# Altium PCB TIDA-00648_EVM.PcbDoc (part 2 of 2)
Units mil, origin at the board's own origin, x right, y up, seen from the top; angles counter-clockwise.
Board outline 2200 x 2000 mil, 4 copper layers (Component Side, Ground Plane, Power Plane, Solder Side), stack 55.6 mil thick; 91 components, 64 nets, 274 pads, 141 vias.
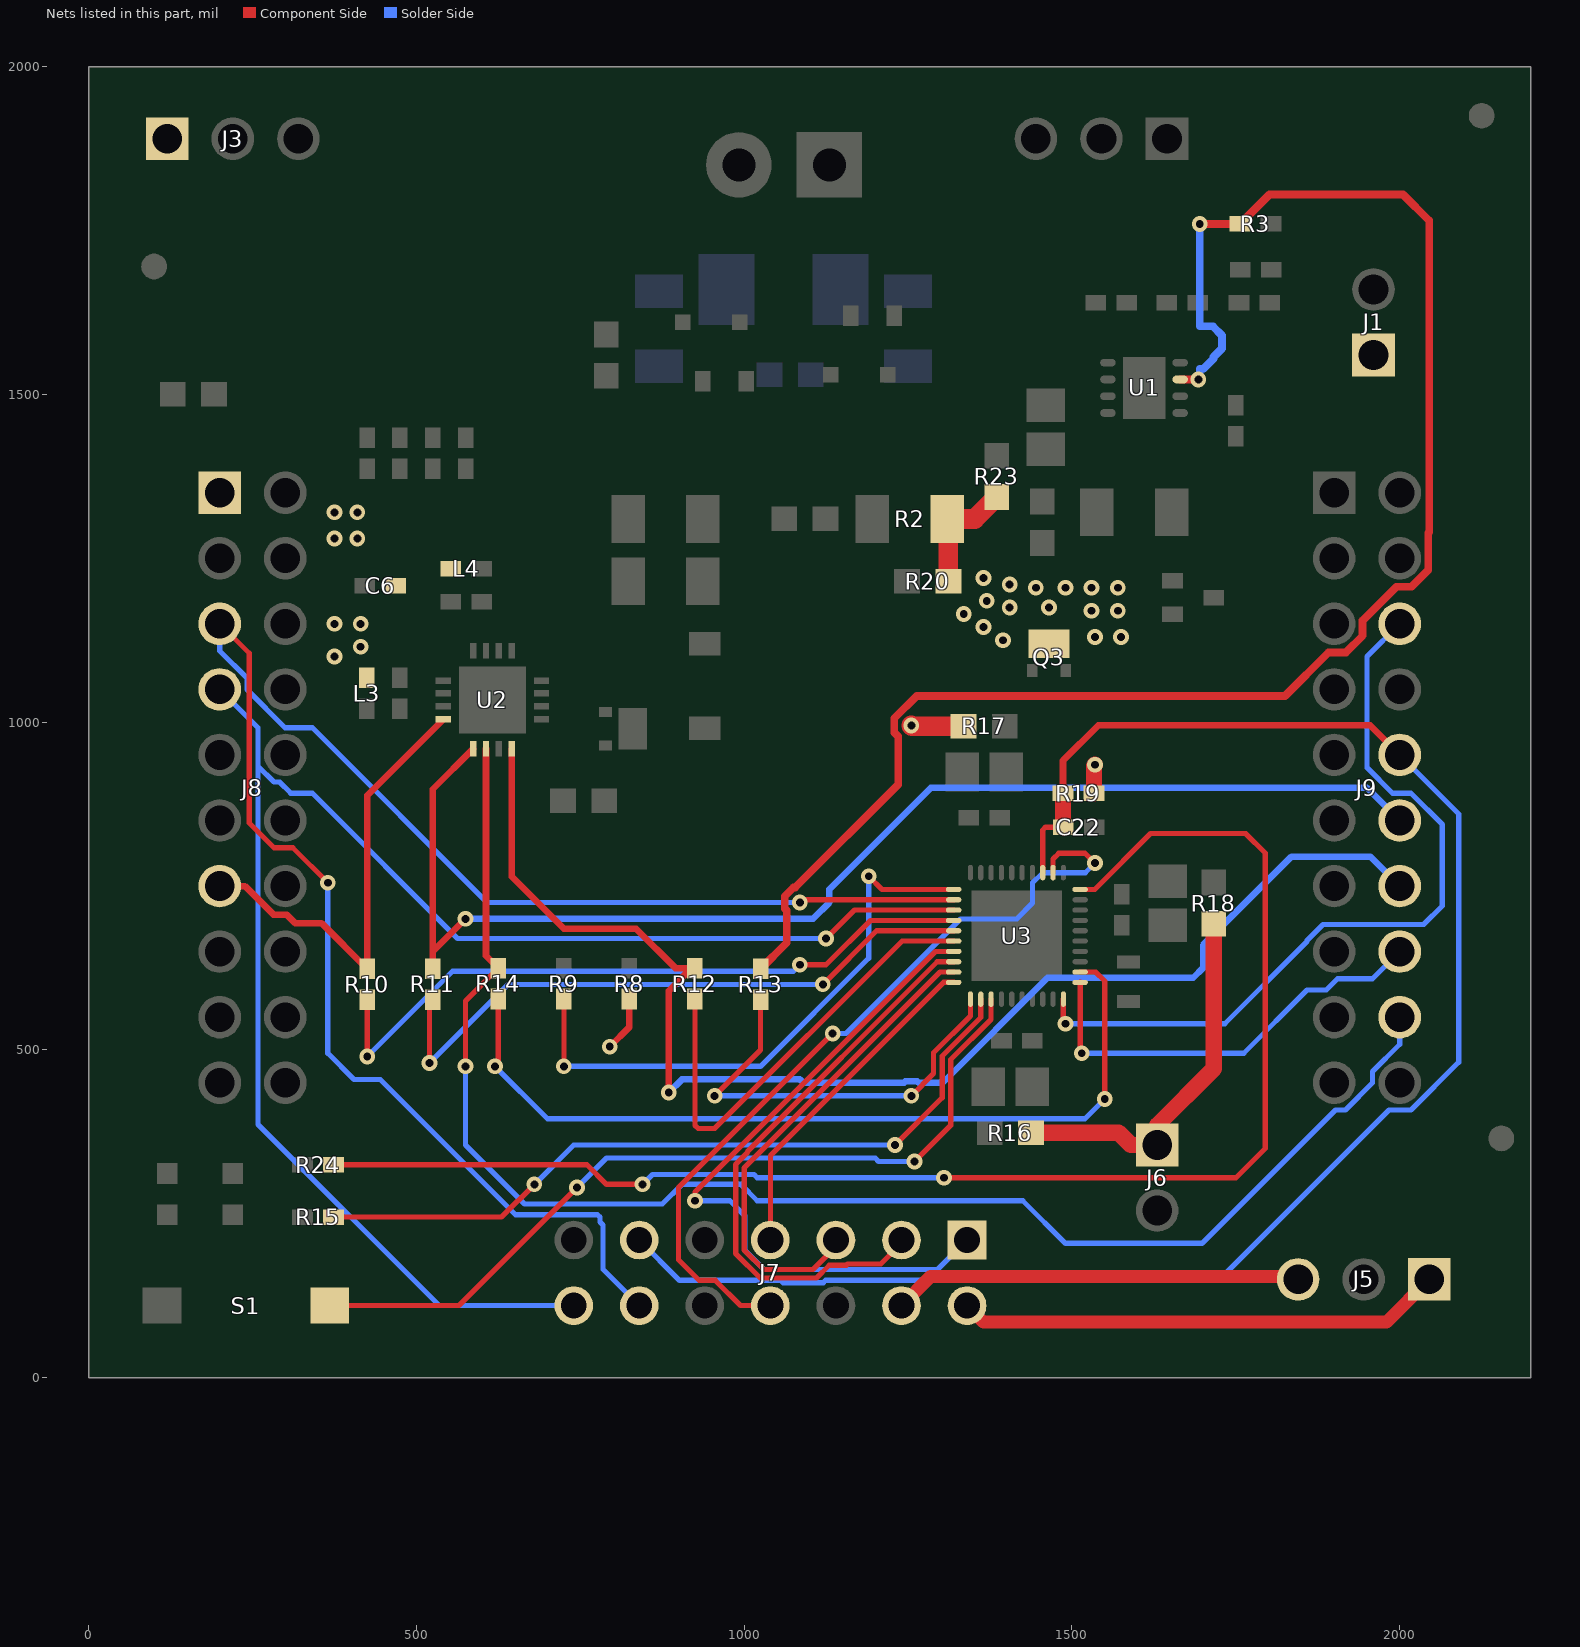
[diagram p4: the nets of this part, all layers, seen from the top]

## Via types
v1: diameter 24, hole 12, Component Side to Solder Side, 125 vias
v2: diameter 19.68, hole 7.87, Component Side to Solder Side, 14 vias
v3: diameter 30, hole 14, Component Side to Solder Side, 1 vias
v4: diameter 30, hole 12, Component Side to Solder Side, 1 vias

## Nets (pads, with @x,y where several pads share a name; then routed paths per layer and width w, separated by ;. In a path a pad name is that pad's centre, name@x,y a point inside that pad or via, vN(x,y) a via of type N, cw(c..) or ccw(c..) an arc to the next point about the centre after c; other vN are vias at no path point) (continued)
NetQ3_3: Q3.3 R2.2 R20.2 R23.1 | length 185.1
  Component Side w30: R20.2@1311.5,1215 1311.5,1308.11 R2.2@1309.61,1310 1351.5,1310 R23.1@1385,1343.5
  other v1: 1395,1125 1535,1130 1575,1130 1365,1145 1335,1165 1530,1170 1570,1170 1405,1175 1465,1175 1370,1185 1445,1205 1490,1205 1530,1205 1570,1205 1405,1210 1365,1220
NetR9_2: R9.2 U3.1 | length 898.9
  Component Side w8: v1(725,475) R9.2@725,577.6 ; v1(1190,765) 1210.2,744.8 U3.1@1319.61,744.8
  Solder Side w8: v1(725,475) 1025,475 1190,640 v1(1190,765)
NetR10_2: R10.2 U3.4 | length 1067
  Component Side w8: v1(425,490) R10.2@425,576.38 ; v1(1085,630) 1125,630 1192.56,697.56 U3.4@1319.61,697.56
  Solder Side w8: v1(425,490) 555,620 1075,620 v1(1085,630)
NetR11_2: R11.2 U3.5 | length 981.6
  Component Side w8: v1(520,480) 520,571.38 R11.2@525,576.38 ; v1(1120,600) 1201.81,681.81 U3.5@1319.61,681.81
  Solder Side w8: v1(520,480) 640,600 v1(1120,600)
NetR12_2: R12.2 U3.6 | length 707.8
  Component Side w8: R12.2@925,577.6 925,385 930,380 955,380 1241.06,666.06 U3.6@1319.61,666.06
NetR13_2: R13.2 U3.11 | length 660.2
  Component Side w8: v1(955,430) 1025,500 R13.2@1025,576.38 ; v1(1255,430) 1289,464 1289,495.77 1345.2,551.97 U3.11@1345.2,577.48
  Solder Side w8: v1(955,430) v1(1255,430)
NetR14_1: R14.1 U3.22 | length 1303.4
  Component Side w8: v1(620,475) 625,480 R14.1@625,577.6 ; U3.22@1512.52,618.82 1536.18,618.82 1550,605 v1(1550,425)
  Solder Side w8: v1(620,475) 700,395 1520,395 v1(1550,425)
NetR15_2: R15.2 U3.12 | length 1178.7
  Component Side w8: R15.2@373.62,245 630,245 v1(680,295) ; v1(1230,355) 1302,427 1302,490.38 1360.94,549.33 U3.12@1360.94,577.48
  Solder Side w8: v1(680,295) 740,355 v1(1230,355)
NetR24_2: R24.2 U3.30 | length 2240.9
  Component Side w8: R24.2@373.62,325 760,325 790,295 v1(845,295) ; v1(1305,305) 1750,305 1795,350 1795,800 1765,830 1620,830 1534.8,744.8 U3.30@1512.52,744.8
  Solder Side w8: v1(845,295) 860,310 1015,310 1020,305 v1(1305,305)
NetS1_1: S1.1 U3.13 | length 1290.6
  Component Side w8: S1.1@367.95,110 565,110 v1(745,290) ; v1(1260,330) 1315,385 1315,485 1376.69,546.69 U3.13@1376.69,577.48
  Solder Side w8: v1(745,290) 790,335 1200,335 1205,330 v1(1260,330) v1@1254.73,324.73
P1.1_UCA0TXD: J7.12 J8.5 U3.2 | length 2750.2
  Component Side w8: J8.5@200,1150 245,1105 245,846.34 282.82,808.52 311.48,808.52 v1(365,755) ; v1(1085,725) 1089.06,729.06 U3.2@1319.61,729.06
  Solder Side w8: J8.5@200,1150 200,1108.66 241.48,1067.18 241.48,1049.86 299.86,991.48 341.48,991.48 607.96,725 v1(1085,725) ; v1(365,755) 365,495 405,455 445,455 651.47,248.53 776.47,248.53 780,245 780,237.5 784.53,232.97 784.53,165.47 J7.12@840,110
P1.2_UCA0RXD: J7.14 J8.7 U3.3 | length 2471.6
  Component Side w8: v1(1125,670) 1168.31,713.31 U3.3@1319.61,713.31
  Solder Side w8: J8.7@200,1050 258.52,991.48 258.52,932.82 ; J7.14@740,110 535,110 258.52,386.48 258.52,932.82 ; v1(1125,670) 562.96,670 341.48,891.48 308.52,891.48 291.48,908.52 282.82,908.52 258.52,932.82
P1.3_UCB0CLK: J8.13 R10.1 U2.4 | length 706.3
  Component Side w10: J8.13@200,750 238.51,750 281.99,706.52 301.96,706.52 315,693.48 355.14,693.48 R10.1@425,623.62 425,888.15 U2.4@541.26,1004.41
P1.4_UCB0SIMO: J9.12 R11.1 U2.5 | length 1972
  Component Side w10: R11.1@525,623.62 525,650 ; v1(575,700) 525,650 ; U2.5@586.54,959.13 525,897.6 525,650
  Solder Side w10: v1(575,700) 1105,700 1130,725 1130,745 1285,900 1950,900 J9.12@2000,850
P1.5_UCB0SOMI: J9.14 R12.1 U2.8 | length 2050.4
  Component Side w10: U2.8@645.59,959.13 645.59,764.41 725,685 835,685 895.16,624.84 R12.1@919.84,624.84 ; v1(885,435) 885,590 R12.1@919.84,624.84 ; R12.1@925,630 R12.1@925,624.84 R12.1@919.84,624.84
  Solder Side w10: v1(885,435) 905,455 1085,455 1090,450 1243.89,450 1245.89,452 1264.11,452 1266.11,450 1302.87,450 1462.87,610 1685,610 1700,625 1700,660 1835,795 1955,795 J9.14@2000,750
P2.5_SPI_CS: J9.6 U3.20 | length 1224
  Component Side w8: U3.20@1486.93,577.48 1486.93,543.07 v1(1490,540)
  Solder Side w8: v1(1490,540) 1733,540 1858.52,665.52 1858.52,667.18 1882.82,691.48 2036.48,691.48 2065,720 2065,843.66 2017.18,891.48 1989.15,891.48 1950,930.63 1950,1100 J9.6@2000,1150 J9.6@1980,1150
P2.6_SPI_CS: J9.16 U3.21 | length 658.3
  Component Side w8: U3.21@1512.52,603.07 1512.52,497.48 v1(1515,495)
  Solder Side w8: v1(1515,495) 1762.04,495 1858.52,591.48 1887.96,591.48 1905,608.52 1958.52,608.52 J9.16@2000,650
P2.7_SPI_CS_DAC: J9.18 R14.2 U2.6 | length 2321.9
  Component Side w8: v1(575,475) 575,574.84 R14.2@625,624.84
  Component Side w10: U2.6@606.22,959.13 606.22,643.62 R14.2@625,624.84
  Solder Side w8: v1(575,475) 575,355 665,265 875,265 905,295 995,295 1020,270 1425,270 1490,205 1698.52,205 1902.04,408.52 1917.18,408.52 1958.52,449.86 1958.52,467.18 2000,508.66 J9.18@2000,550
PG: R3.1 R13.1 U1.3 | length 2625.2
  Component Side w12: R13.1@1025,623.62 1065,663.62 1065,712.47 1062,715.47 1062,734.53 1075.47,748 1078,748 1235,905 1235,978.23 1229,984.23 1229,1005.77 1263.23,1040 1825,1040 1891.52,1106.52 1918.01,1106.52 1943.48,1131.99 1943.48,1154.97 1995.03,1206.52 2018.01,1206.52 2043.48,1231.99 2043.48,1288.48 2045,1290 2045,1765 2005,1805 1801.38,1805 R3.1@1756.38,1760 v1(1695,1760) ; U1.3@1665.12,1522.8 v1(1692.8,1522.8)
  Solder Side w12: v1(1692.8,1522.8) 1695,1525 1695,1539.13 1700.72,1539.13 1715.87,1554.28 1715.87,1556.93 1729,1570.06 1729,1589.94 1714.94,1604 1695.06,1604 1695,1603.94 v1(1695,1760)
RST: C22.1 J7.11 J9.10 R19.1 U3.33 | length 2676.3
  Component Side w8: U3.33@1455.43,770.39 1455.43,835.43 1459.84,839.84 C22.1@1486.57,839.84
  Component Side w10: R19.1@1486.38,891.65 1486.38,941.38 1540,995 1955,995 J9.10@2000,950
  Component Side w25: R19.1@1486.38,891.65 1486.38,840.03 C22.1@1486.57,839.84
  Solder Side w8: J7.11@840,210 901.47,148.53 1055.96,148.53 1059.49,145 1120.51,145 1124.04,148.53 1723.53,148.53 1983.52,408.52 2017.18,408.52 2090,481.34 2090,860 J9.10@2000,950
TCK: J7.7 U3.10 | length 518
  Component Side w8: J7.7@1040,210 1040,338.99 1304.08,603.07 U3.10@1319.61,603.07
TDI: J7.3 U3.8 | length 892.9
  Component Side w8: J7.3@1240,210 1240,205 1208.31,173.31 1157.79,173.31 1155.96,171.47 1129.86,171.47 1110.38,152 1024.62,152 987,189.62 987,325.38 1005,343.38 1005,345 1294.57,634.57 U3.8@1319.61,634.57
TDO: J7.1 U3.7 | length 1068.1
  Component Side w8: v1(925,270) 925,283.38 1291.93,650.31 U3.7@1319.61,650.31
  Solder Side w8: v1(925,270) 978.38,270 1001.47,246.91 1001.47,194.04 1030.51,165 1295,165 J7.1@1340,210
TEST: J7.8 U3.32 | length 1231.5
  Component Side w8: J7.8@1040,110 994.49,110 955.96,148.53 931.47,148.53 900,180 900,290 v1(1135,525) ; U3.32@1471.18,770.39 1471.18,791.18 1480,800 1520,800 v1(1535,785)
  Solder Side w8: v1(1135,525) 1155.15,525 1330.08,699.92 1415.71,699.92 1440,724.22 1440,755 1455.39,770.39 1520.39,770.39 v1(1535,785)
TMS: J7.5 U3.9 | length 745.3
  Component Side w8: J7.5@1140,210 1140,200 1105,165 1030,165 1000,195 1000,320 1298.82,618.82 U3.9@1319.61,618.82
VCC: C6.1 J1.1 J3.1 J6.1 J8.1 L3.1 L4.1 R8.1 R16.2 R17.2 R18.2 R19.2 | length 782.3
  Component Side w10: v1(795,505) 825,535 R8.1@825,577.6
  Component Side w25: R16.2@1437.56,373.94 1571.06,373.94 1590,355 J6.1@1630,355 1630,385 1716.06,471.06 R18.2@1716.06,692.44 ; R19.2@1533.62,891.65 1533.62,933.62 v1(1535,935)
  Component Side w30: v1(1255,995) 1256.06,993.94 R17.2@1334.57,993.94
  other v1: 375,1100 415,1115 375,1150 415,1150 375,1280 410,1280 375,1320 410,1320
VCC_TARGET: J5.3 J7.4 | length 628
  Component Side w20: J7.4@1240,110 1284.53,154.53 1845,154.53 J5.3@1845,150
VCC_TOOL: J5.1 J7.2 | length 742.3
  Component Side w20: J7.2@1340,110 1365,85 1980,85 J5.1@2045,150
pads on no net: FID1.1 FID2.1 FID3.1 J7.6 J7.10 J7.13 J8.2 J8.6 J8.8 J8.9 J8.10 J8.11 J8.12 J8.14 J8.16 J8.17 J8.18 J8.19 J8.20 J9.1 J9.3 J9.4 J9.5 J9.7 J9.8 J9.9 J9.11 J9.13 J9.15 J9.17 J9.19 LBL1.0 SH-J1.0 SH-J2.0 SH-J3.0 SH-J4.0 SH-J5.0 U1.6 U2.11 U3.14 U3.15 U3.16 U3.19 U3.23 U3.24 U3.28 U3.29 U3.31 U3.34 U3.35 U3.36 U3.38 U3.39

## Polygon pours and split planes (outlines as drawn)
NetC3_1 on Solder Side "Bottom Layer-No Net 1" (solid, remove dead copper, pour order 24): 1285.43,1570 1101.3,1570 ccw(c1101.3,1548.7) 1080,1548.7 1080,1450 ccw(c1110,1450) 1110,1420 1130,1420 ccw(c1130,1450) 1160,1450 1160,1479.6 cw(c1185.9,1479.6) 1185.9,1505.5 1275.5,1505.5 ccw(c1275.5,1520) 1290,1520
NetC3_2 on Solder Side "Bottom Layer-No Net" (solid, remove dead copper, pour order 27): 834.57,1570 905.43,1570 1030.86,1570 cw(c1030.86,1535.86) 1055,1560 cw(c1042.93,1547.93) 1060,1547.93 1060,1430 cw(c1047.93,1430) 1056.46,1421.46 1055,1420 1040,1420 1007.07,1420 cw(c1007.07,1437.07) 995,1425 cw(c1007.07,1437.07) 990,1437.07 990,1480 ccw(c953.79,1480) 979.39,1505.61 970,1515 880,1515 835,1515
NetD7_2 on Solder Side "Component Side-No Net 3" (solid, remove dead copper, pour order 26): 800,1095 800,745 810,735 1020,735 1085,785 1099.4,823.96 1210.82,918.5 1199.99,1095
NetQ3_3 on Solder Side "Component Side-No Net 6" (solid, remove dead copper, pour order 23): 1293.19,1234.11 1293.19,1101.81 1310,1085 1406.44,1085 1610,1075 1625,1090 1625,1100 1625,1235 1635,1245
NetD3_1 on Solder Side "Solder Side-No Net 2" (solid, remove dead copper, pour order 22): 1080,1950 1080,1720 1085,1715 1375,1715 1375,1890 1315,1950
NetD3_2 on Solder Side "Top Overlay-No Net" (solid, remove dead copper, pour order 20): 1035,1950 590,1950 535,1895 535,1715 1030,1715 1035,1710
NetC3_2 on Component Side "Bottom Layer-No Net 2" (solid, remove dead copper, pour order 29): 1040,1420 1014.14,1420 cw(c1014.14,1454.14) 990,1430 cw(c1002.07,1442.07) 985,1442.07 985,1510 985,1548.54 ccw(c950.44,1548.54) 974.88,1572.98 974.88,1612.63 cw(c992.37,1612.63) 980,1625 990,1625 995,1625 990,1625 cw(c993.97,1598.36) 1010,1620 1043.36,1586.64 cw(c1015.28,1558.55) 1055,1558.54 1055,1497.07 ccw(c1072.07,1497.07) 1060,1485 1060,1432.07 cw(c1042.94,1432.07) 1055,1420 1045,1420
NetD1_1 on Component Side "Top Layer-No Net" (solid, remove dead copper, pour order 31): 922.76,1539.68 cw(c936.77,1525.67) 936.77,1545.49 1235.89,1545.49 1240.71,1540.67 cw(c1170,1469.96) 1270,1469.96 1270,1263.74 cw(c1260.97,1272.77) 1260.97,1260 1100,1260 1063.92,1260 cw(c1063.92,1360) 993.21,1289.29 937.09,1345.41 cw(c971.68,1380.01) 922.76,1380.01 922.76,1500.32
NetC3_1 on Component Side "Top Layer-No Net 1" (solid, remove dead copper, pour order 30): 1130,1419.74 1110,1419.74 cw(c1110,1450) 1088.6,1428.6 cw(c1099.16,1439.16) 1084.23,1439.16 1084.23,1490.12 1084.23,1571.17 cw(c1178.25,1571.17) 1111.77,1637.65 cw(c1115.82,1633.6) 1115.82,1639.33 1180,1639.33 1183.86,1635.47 ccw(c1185,1636.62) 1185,1635 1185,1598.28 cw(c1116.72,1598.28) 1165,1550 ccw(c1189.14,1525.86) 1155,1525.86 1155,1520 1155,1512.07 ccw(c1172.07,1512.07) 1160,1500 1160,1449.38 cw(c1130.62,1449.38) 1151.4,1428.6 1150.45,1427.65 cw(c1131.97,1446.13) 1131.97,1420
NetC1_1 on Component Side "Component Side-No Net" (solid, remove dead copper, pour order 17): 2010,1619.84 2008.5,1618.35 1765,1618.35 1765,1732.83 1765.4,1733.58 1775,1735 2010,1735
NetC1_1 on Component Side "Component Side-No Net 1" (solid, remove dead copper, pour order 21): 1728.35,1410.79 1815.79,1410.79 1825,1420 1865,1460 1865,1550 1865,1635 1860,1640 1780,1640 1780,1490 1765,1475 1750,1460 1746,1460 1734,1460 1728.73,1441.8 1726.85,1413.91 1727.06,1413.17
GND on Component Side "Component Side-No Net 2" (solid, remove dead copper, pour order 25): 560.04,1024.09 452.76,1024.09 452.76,1092.76 460,1100 510,1150 510,1200 515,1205 515.59,1205.59 576.06,1205.59 576.06,1101.46 559.65,1085.04
VCC on Component Side "Solder Side-No Net" (solid, remove dead copper, pour order 28): 104,1446 347,1446 357.1,1421.62 389.64,1372.91 453.41,1295.21 496.14,1275 580,1275 580,1155 585,1150 480,1045 380,1045 355,1045 350,1050 345,1055 345,1250 155.63,1250 103.73,1300.62 100.25,1440.15
NetD7_2 on Component Side "Solder Side-No Net 1" (solid, remove dead copper, pour order 19): 805,1090 810,1085 810,735 1010,735 1070,755 1204.08,910.9 1205.9,1027.58 1204.08,1080 1139.7,1090
LOOP_P on Component Side "Component Side-No Net 4" (solid, remove dead copper, pour order 32): 850,1350 1095,1350 1125,1320 1125,1080 841.66,1080 831.66,1090
NetQ3_3 on Component Side "Component Side-No Net 5" (solid, remove dead copper, pour order 18): 1280,1233.68 1290,1223.68 1290,1075 1630,1075 1630,1245
GND on Ground Plane (split plane): 2179.9,20.1 20.1,20.1 20.1,1979.9 2179.9,1979.9
VCC on Power Plane (split plane): 2179.9,20.1 20.1,20.1 20.1,1979.9 2179.9,1979.9

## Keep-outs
Keep-Out Layer:
  lines w20: -10,0 ccw(c0,0) 0,-10 ; -10,0 ccw(c0,0) 0,-10 ; -10,0 -10,2000 ; -10,2000 cw(c0,2000) 0,2010 ; -10,2000 cw(c0,2000) 0,2010 ; 0,-10 2200,-10 ; 0,2010 2200,2010 ; 2200,-10 ccw(c2200,0) 2210,0 ; 2200,-10 ccw(c2200,0) 2210,0 ; 2200,2010 cw(c2200,2000) 2210,2000 ; 2200,2010 cw(c2200,2000) 2210,2000 ; 2210,0 2210,2000
  text ".Layer_Name" at 577,-858.49 h60

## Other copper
Component Side:
  text ".Layer_Name" at 577,-858.49 h60
Solder Side:
  text ".Layer_Name" at 577,-858.49 h60

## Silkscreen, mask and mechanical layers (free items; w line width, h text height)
Top Overlay:
  region: 350,1640 50,1640 50,1540 350,1540
  lines w10: 1580,890 1603,968 ; 1670,805 1690,835 ; 1575,785 1600,820 1575,785
  text ".PCB_Rev" at 100,1030 h60 r90
  text ".PRJ_Number" at 100,400 h60 r90
  text "Ext" at 1780,35 h40
  text "Int" at 2020,35 h40
  text ".Layer_Name" at 577,-858.49 h60
Bottom Overlay:
  text ".Layer_Name" at 577,-858.49 h60
Top Paste:
  text ".Layer_Name" at 577,-858.49 h60
Bottom Paste:
  text ".Layer_Name" at 577,-858.49 h60
Top Solder:
  text ".Layer_Name" at 577,-858.49 h60
  text ".Layer_Name" at 577,-858.49 h60
Bottom Solder:
  text ".Layer_Name" at 577,-858.49 h60
Drill Guide:
  text ".Layer_Name" at 577,-858.49 h60
Mechanical 1:
  the board outline again, w10
  text ".Layer_Name" at 577,-858.49 h60
Mechanical 2:
  rectangle: 125,-400 500,-275
  rectangle: 0,-275 125,-150
  lines w7: 0,-275 1000,-275 ; 125,-400 125,-150 ; 250,-400 250,-150 ; 500,-400 500,-150 ; 750,-400 750,-150 ; 0,-400 0,-150 1000,-150 1000,-400 0,-400
  text ".Layer_Name" at 577,-858.49 h60
Mechanical 3:
  text ".Layer_Name" at 577,-858.49 h60
Mechanical 4:
  text ".Layer_Name" at 577,-858.49 h60
Mechanical 5:
  lines w10: -292,-930.17 6308,-930.17 ; -292,-726.83 6310,-726.83 ; -292,-523.5 -292,-1133.5 3713,-1133.5 6310,-1133.5 6310,-523.5 -291.5,-523.5 -291.5,-1133.5 1284,-1133.5 ; 2173,-1133.5 2173,-523.5 ; 3440,-726.83 3440,-523.5 ; 4280,-726.83 4280,-523.5 ; 4902,-1140 4902,-937.17
  text "COMPONENTS MARKED 'DNP' SHOULD NOT BE POPULATED." at 1153.5,-318.5 h60
  text "ASSEMBLY VARIANT:" at 1153,-434 h60
  text ".VariantName" at 2189,-434 h60
  text "PCB VIEWED FROM TOP SIDE" at -228.5,-655.67 h60
  text "BOARD #:" at 2248,-655.67 h60
  text ".PRJ_Number" at 2793.5,-655.67 h60
  text "REV:" at 3638,-655.67 h60
  text ".PCB_Rev" at 3929.5,-655.67 h60
  text "SVN REV:" at 4476,-655.67 h60
  text ".VersionControl_RevNumber" at 4982,-655.67 h60
  text "TID #:" at 2248,-859 h60
  text ".TID" at 2793.5,-859 h60
  text "PLOT NAME =" at -228.5,-1064.34 h60
  text ".plot_File_Name" at 577,-1064.34 h60
  text "GENERATED    :" at 2250,-1064.34 h60
  text ".Print_Date" at 3119.5,-1064.34 h60
  text ".Print_Time" at 3848.5,-1064.34 h60
  text "TEXAS INSTRUMENTS" at 5113,-1064.34 h60
Mechanical 6:
  lines w10: -292.5,-727.33 6309.5,-727.33 ; -290.5,-930.67 6309.5,-930.67 ; 1115.5,-1140.5 1115.5,-937.67 ; 1737.5,-727.33 1737.5,-524 ; 2577.5,-727.33 2577.5,-524 ; 3844.5,-1134 3844.5,-524 ; 4733.5,-1134 6309,-1134 6309,-524 -292.5,-524 -292.5,-1134 2304.5,-1134 6309.5,-1134 6309.5,-524
  text "COMPONENTS MARKED 'DNP' SHOULD NOT BE POPULATED." at 6102,-318 h60
  text ".VariantName" at 5058,-434 h60
  text "ASSEMBLY VARIANT:" at 6097,-434 h60
  text ".VersionControl_RevNumber" at 1035.5,-656.17 h60
  text "SVN REV:" at 1541.5,-656.17 h60
  text ".PCB_Rev" at 2088,-656.17 h60
  text "REV:" at 2379.5,-656.17 h60
  text ".PRJ_Number" at 3224,-656.17 h60
  text "BOARD #:" at 3769.5,-656.17 h60
  text "PCB VIEWED FROM BOTTOM SIDE" at 6246,-656.17 h60
  text ".TID" at 3224,-859.5 h60
  text "TID #:" at 3769.5,-859.5 h60
  text "TEXAS INSTRUMENTS" at 904.5,-1064.84 h60
  text ".Print_Time" at 2169,-1064.84 h60
  text ".Print_Date" at 2898,-1064.84 h60
  text "GENERATED    :" at 3767.5,-1064.84 h60
  text ".plot_File_Name" at 5440.5,-1064.84 h60
  text "PLOT NAME =" at 6246,-1064.84 h60
Mechanical 9:
  drawing of 57 lines, arcs and shapes, not listed
  text "1" at 739.84,8036.5 h70
  text "2" at 3235.5,8036.5 h70
  text "3" at 5724.84,8036.5 h70
  text "4" at 8231.51,8036.5 h70
  text "5" at 10730.5,8036.5 h70
  text "6" at 13235.5,8036.5 h70
  text "A" at -416.5,6893.5 h70
  text "A" at 14383.5,6893.5 h70
  text "B" at -416.5,4513.5 h70
  text "B" at 14383.5,4513.5 h70
  text "C" at -416.5,2138.5 h70
  text "C" at 14383.5,2138.5 h70
  text "PROJECT TITLE:" at 11343.5,277.5 h45
  text ".PRJ_Title" at 11393.5,144.17 h70
  text "DESIGNED FOR:" at 11343.5,-23.5 h45
  text ".PRJ_Customer" at 11393.5,-163.5 h70
  text "D" at -416.5,-231.5 h70
  text "D" at 14383.5,-231.5 h70
  text "FILE NAME:" at 11343.5,-323.5 h45
  text ".PCB_File_Name_No_Path" at 11393.5,-443.5 h70
  text "Texas Instruments (TI) and/or its licensors do not warrant the accuracy or completeness of this specification" at 6374,-605.34 h45
  text "ENGINEER:" at 11343.5,-613.5 h45
  text "LAYOUT BY:" at 12848.5,-613.5 h45
  text "or any information contained therein. TI and/or its licensors do not warrant that this design will meet" at 6329.01,-718 h45
  text ".PRJ_Engineer" at 11393.5,-768.49 h70
  text ".PCB_Layout" at 12899,-768.49 h70
  text "the specifications, will be suitable for your application or fit for any particular purpose, or will operate in" at 6329.01,-830.67 h45
  text ".Layer_Name" at 577,-858.49 h60
  text "ALTIUM DESIGNER VERSION:" at 12848.5,-923.5 h45
  text "an implementation. TI and/or its licensors do not warrant that the design is production worthy. You should" at 6329.01,-943.33 h45
  text "completely validate and test your design implementation to confirm the system functionality for your application." at 6374,-1056 h45
  text ".print_Scale" at 11393.5,-1056.83 h70
  text ".Application_BuildNumber" at 12899,-1056.83 h70
  text "1" at 739.84,-1263.5 h70
  text "2" at 3235.5,-1263.5 h70
  text "3" at 5724.84,-1263.5 h70
  text "4" at 8231.51,-1263.5 h70
  text "5" at 10730.5,-1263.5 h70
  text "6" at 13235.5,-1263.5 h70
Mechanical 10:
  drawing of 185 lines, arcs and shapes, not listed
  text "DESIGN INFORMATION" at 12381.02,5910 h60
  text "MIN. TRACK WIDTH:" at 11736.46,5730 h60
  text "8" at 12832.7,5730 h60
  text "MIL" at 12987.46,5730 h60
  text "MIN. CLEARANCE:" at 11736.46,5598 h60
  text "0.2" at 12772.7,5598 h60
  text "mm" at 12987.46,5598 h60
  text "MIN. VIA PAD SIZE:" at 11736.46,5466 h60
  text "24" at 12802.71,5466 h60
  text "MIL" at 12987.46,5466 h60
  text "0.05mm (2MIL)" at 12431.46,5324.29 h60
  text "MINIMUM ANNULAR RING" at 11407.23,5320 h60
  text "EXTERNAL" at 13139.46,5320 h60
  text "PER" at 11607.23,5202 h60
  text "IPC-D-275 CLASS 2 LEVEL C" at 11827.23,5202 h60
  text "MIL, HOLES" at 13315.46,5089.71 h60
  text "+/-" at 12923,5089 h60
  text "+/-" at 13777,5089 h60
  text "REGISTRATION TOLERANCES:" at 11407.23,5084 h60
  text "METAL" at 12607,5084 h60
  text "5" at 13183.2,5084 h60
  text "3" at 14016.2,5084 h60
  text "MIL" at 14132.46,5084 h60
  text "MATERIAL:" at 11332.46,4874.54 h60
  text "FR-4 High Tg" at 12318.9,4734.21 h60
  text "FR-408" at 11753.46,4725.64 h60
  text "X" at 12165.46,4725.64 h60
  text "OTHER" at 13241.46,4725.64 h60
  text "62 MIL (1.6mm) +/-10%" at 12073.56,4562.92 h60
  text "THICKNESS:" at 11407.23,4558.64 h60
  text "X" at 11945.4,4558.64 h60
  text "OTHER" at 13358.46,4558.64 h60
  text "TOLERANCE:" at 11407.23,4400.64 h60
  text "X" at 12246.53,4400.64 h60
  text "ANSI IPC-6012 TYPE 3 CLASS 2" at 12433.48,4400.64 h60
  text "OTHER +/-" at 12433.46,4244.64 h60
  text "BOW & TWIST:" at 11407.23,4087.64 h60
  text "X" at 12246.53,4087.64 h60
  text "ANSI IPC-6012 TYPE 3 CLASS 2" at 12433.48,4087.64 h60
  text "OTHER +/-" at 12433.46,3929.13 h60
  text "DRILLING:" at 11332.46,3790.64 h60
  text "REFERENCE:" at 11407.23,3673.64 h60
  text "X" at 12055.46,3673.64 h60
  text "AS SHOWN" at 12242.46,3673.64 h60
  text "X" at 12956.46,3673.64 h60
  text "NC_DRILL FILES" at 13093.46,3673.64 h60
  text "PTH MIN COPPER THICKNESS:" at 11407.23,3515.64 h60
  text "X" at 12757.46,3515.64 h60
  text "1MIL" at 12894.46,3515.64 h60
  text "OTHER" at 13391.46,3515.64 h60
  text "BOARD FINISH:" at 11332.46,3356.64 h60
  text "SILKSCREEN:" at 11487.68,3238.64 h60
  text "X" at 12436.46,3238.64 h60
  text "TOP" at 12562.46,3238.64 h60
  text "X" at 12946.46,3238.64 h60
  text "BOTTOM" at 13073.46,3238.64 h60
  text "SILKSCREEN COLOR:" at 11487.68,3071.64 h60
  text "X" at 12435.42,3071.64 h60
  text "WHITE" at 12562.46,3071.64 h60
  text "OTHER" at 13073.46,3071.64 h60
  text "SOLDER RESIST COLOR:" at 11487.68,2901.64 h60
  text "X" at 12055.42,2742.44 h60
  text "GREEN" at 12182.46,2742.44 h60
  text "BLUE" at 12773.46,2742.44 h60
  text "OTHER" at 13311.46,2742.44 h60
  text "IMMERSION GOLD (ENIG)" at 12393.46,2553.92 h60
  text "ENEPIG" at 13731,2550.64 h60
  text "SURFACE FINISH:" at 11332.46,2549.64 h60
  text "X" at 12206.51,2549.64 h60
  text "IMM. TIN/SILVER OR EQUIV" at 11662,2392.64 h60
  text "OTHER" at 13093.46,2392.64 h60
  text "ARRAY/PANEL:" at 11332.46,2213.64 h60
  text "CUT AND TRIM PER MECH LAYER 1" at 12393.46,2209.35 h60
  text "N.C. ROUTE" at 12393.46,2057.64 h60
  text "X" at 13072.46,2057.64 h60
  text "V. SCORE" at 13259.46,2057.64 h60
  text "CERTIFICATION:" at 11332.46,1920.64 h60
  text "MATERIALS AND WORKMANSHIP FOR ALL PCBS" at 12057.46,1920.64 h60
  text "TO MEET OR EXCEED THE REQUIREMENTS OF:" at 12057.46,1822.64 h60
  text "X" at 11683.96,1686.13 h60
  text "ANSI IPC-A-600F CLASS ->" at 11822.96,1686.13 h60
  text "X" at 13462.02,1686.13 h60
  text "2" at 13580.96,1686.14 h60
  text "1" at 13265.96,1684.64 h60
  text "3" at 13934.96,1684.64 h60
  text "X" at 11686.02,1526.64 h60
  text "UL 94V-0" at 11822.96,1526.64 h60
  text "X" at 12498.02,1526.64 h60
  text "RoHS" at 12634.96,1526.64 h60
  text "OTHER" at 13279.36,1526.64 h60
  text "PER ORDER" at 13676.42,1526.64 h60
  text "ADDITIONAL REQUIREMENTS:" at 11332.46,1385.64 h60
  text "MICROSECTION:" at 11407.23,1270.64 h60
  text "YES" at 12312.96,1270.64 h60
  text "REQUIRED" at 13174.46,1114.49 h60
  text "BARE BOARD ELEC. TEST:" at 11407.23,1111.64 h60
  text "NONE" at 12712.96,1111.64 h60
  text "X" at 13047.46,1111.64 h60
  text "PER ORDER" at 13766.46,1111.64 h60
  text "MANUFACTURER'S UL:" at 11407.23,954.64 h60
  text "RAIL" at 12572.96,950.35 h60
  text "METAL" at 13064.77,950.35 h60
  text "X" at 13440,950 h60
  text "SILK" at 13576.46,950.35 h60
  text ".Layer_Name" at 577,-858.49 h60
Mechanical 11:
  lines w10: -292,-930.17 6308,-930.17 ; -292,-726.83 6310,-726.83 ; -292,-523.5 -292,-1133.5 3713,-1133.5 6310,-1133.5 6310,-523.5 -291.5,-523.5 -291.5,-1133.5 1284,-1133.5 ; 2173,-1133.5 2173,-523.5 ; 3440,-726.83 3440,-523.5 ; 4280,-726.83 4280,-523.5 ; 4902,-1140 4902,-937.17
  text "ALL ARTWORK VIEWED FROM TOP SIDE" at -228.5,-655.67 h60
  text "BOARD #:" at 2248,-655.67 h60
  text ".PRJ_Number" at 2793.5,-655.67 h60
  text "REV:" at 3638,-655.67 h60
  text ".PCB_Rev" at 3929.5,-655.67 h60
  text "SVN REV:" at 4476,-655.67 h60
  text ".VersionControl_RevNumber" at 4982,-655.67 h60
  text "LAYER NAME =" at -228.5,-858.49 h60
  text "TID #:" at 2248,-859 h60
  text ".TID" at 2793.5,-859 h60
  text "PLOT NAME =" at -228.5,-1064.34 h60
  text ".plot_File_Name" at 577,-1064.34 h60
  text "GENERATED    :" at 2250,-1064.34 h60
  text ".Print_Date" at 3119.5,-1064.34 h60
  text ".Print_Time" at 3848.5,-1064.34 h60
  text "TEXAS INSTRUMENTS" at 5113,-1064.34 h60
Mechanical 12:
  drawing of 295 lines, arcs and shapes, not listed
  text "Layer" at 9545.58,7650 h60
  text "Name" at 9955.49,7650 h60
  text "Material" at 10895.23,7650 h60
  text "Thickness" at 11755,7650 h60
  text "Constant" at 12404.84,7650 h60
  text "Board Layer Stack" at 12974.7,7650 h60
  text "1" at 9545.58,7530 h60
  text "Top Overlay" at 9955.49,7530 h60
  text "2" at 9545.58,7410 h60
  text "Top Solder" at 9955.49,7410 h60
  text "Solder Resist" at 10895.23,7410 h60
  text "0.40mil" at 11755,7410 h60
  text "3.5" at 12404.84,7410 h60
  text "3" at 9545.58,7290 h60
  text "Component Side" at 9955.49,7290 h60
  text "Copper" at 10895.23,7290 h60
  text "1.40mil" at 11755,7290 h60
  text "4" at 9545.58,7170 h60
  text "Dielectric 1" at 9955.49,7170 h60
  text "FR-4" at 10895.23,7170 h60
  text "10.00mil" at 11755,7170 h60
  text "4.2" at 12404.84,7170 h60
  text "5" at 9545.58,7050 h60
  text "Ground Plane" at 9955.49,7050 h60
  text "Copper" at 10895.23,7050 h60
  text "1.40mil" at 11755,7050 h60
  text "6" at 9545.58,6930 h60
  text "Dielectric 3" at 9955.49,6930 h60
  text "FR-4" at 10895.23,6930 h60
  text "30.00mil" at 11755,6930 h60
  text "4.2" at 12404.84,6930 h60
  text "7" at 9545.58,6810 h60
  text "Power Plane" at 9955.49,6810 h60
  text "Copper" at 10895.23,6810 h60
  text "1.40mil" at 11755,6810 h60
  text "8" at 9545.58,6690 h60
  text "Dielectric 4" at 9955.49,6690 h60
  text "FR-4" at 10895.23,6690 h60
  text "10.00mil" at 11755,6690 h60
  text "4.2" at 12404.84,6690 h60
  text "9" at 9545.58,6570 h60
  text "Solder Side" at 9955.49,6570 h60
  text "Copper" at 10895.23,6570 h60
  text "1.40mil" at 11755,6570 h60
  text "10" at 9545.58,6450 h60
  text "Bottom Solder" at 9955.49,6450 h60
  text "Solder Resist" at 10895.23,6450 h60
  text "0.40mil" at 11755,6450 h60
  text "3.5" at 12404.84,6450 h60
  text "11" at 9545.58,6330 h60
  text "Bottom Overlay" at 9955.49,6330 h60
  text ".Layer_Name" at 577,-858.49 h60
Mechanical 13:
  text ".Layer_Name" at 577,-858.49 h60
Mechanical 14:
  text ".Layer_Name" at 577,-858.49 h60
Mechanical 15:
  text ".Layer_Name" at 577,-858.49 h60
Mechanical 16:
  text ".Layer_Name" at 577,-858.49 h60
Drill Drawing:
  circle w1: c3072.82,1455.77 r24.92
  lines w1: 3047.91,695.81 3060.37,695.81 3060.37,683.35 3085.28,683.35 3085.28,695.81 3097.74,695.81 3097.74,720.72 3085.28,720.72 3085.28,733.18 3060.37,733.18 3060.37,720.72 3047.91,720.72 3047.91,695.81 ; 3047.91,832.85 3072.82,845.31 3097.74,832.85 3085.28,857.77 3097.74,882.68 3072.82,870.22 3047.91,882.68 3060.37,857.77 3047.91,832.85 ; 3047.91,1032.18 3097.74,1032.18 3072.82,982.35 3047.91,1032.18 ; 3047.91,1131.85 3097.74,1131.85 3097.74,1181.68 3047.91,1181.68 3047.91,1131.85 ; 3047.91,1281.35 3097.74,1281.35 3097.74,1331.18 3047.91,1331.18 3047.91,1281.35 ; 3057.88,1291.32 3087.78,1291.32 3087.78,1321.22 3057.88,1321.22 3057.88,1291.32
  lines w12: 2980,638.5 5098.44,638.5 ; 2980,1535.5 5098.44,1535.5 ; 3350.51,489 3350.51,1685 ; 3707.67,489 3707.67,1685 ; 4369.15,489 4369.15,1685 ; 4653.35,489 4653.35,1685 ; 2980,489 5098.44,489 5098.44,1685 2980,1685 2980,489
  text "Symbol" at 3069.7,1580.35 h72
  text "Quantity" at 3395.36,1580.35 h72
  text "Finished Hole Size" at 3752.52,1580.35 h72
  text "Plated" at 4414,1580.35 h72
  text "Hole Type" at 4698.2,1580.35 h72
  text "14" at 3395.36,1430.85 h60
  text "7.87mil (0.200mm)" at 3752.52,1430.85 h60
  text "PTH" at 4414,1430.85 h60
  text "Round" at 4698.2,1430.85 h60
  text "126" at 3395.36,1281.35 h60
  text "12.00mil (0.305mm)" at 3752.52,1281.35 h60
  text "PTH" at 4414,1281.35 h60
  text "Round" at 4698.2,1281.35 h60
  text "1" at 3395.36,1131.85 h60
  text "14.00mil (0.356mm)" at 3752.52,1131.85 h60
  text "PTH" at 4414,1131.85 h60
  text "Round" at 4698.2,1131.85 h60
  text "14" at 3395.36,982.35 h60
  text "39.37mil (1.000mm)" at 3752.52,982.35 h60
  text "PTH" at 4414,982.35 h60
  text "Round" at 4698.2,982.35 h60
  text "53" at 3395.36,832.85 h60
  text "45.28mil (1.150mm)" at 3752.52,832.85 h60
  text "PTH" at 4414,832.85 h60
  text "Round" at 4698.2,832.85 h60
  text "2" at 3395.36,683.35 h60
  text "50.00mil (1.270mm)" at 3752.52,683.35 h60
  text "PTH" at 4414,683.35 h60
  text "Round" at 4698.2,683.35 h60
  text "210 Total" at 3395.36,533.85 h60
  text ".Layer_Name" at 577,-858.49 h60

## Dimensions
0,0 to 2200,0 on Mechanical 2
0,0 to 0,2000 on Mechanical 2
0,-400 to 1000,-400 on Mechanical 2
